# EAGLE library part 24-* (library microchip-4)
Serial EEPROM 32 K/64 K, 1.8 V, I2C
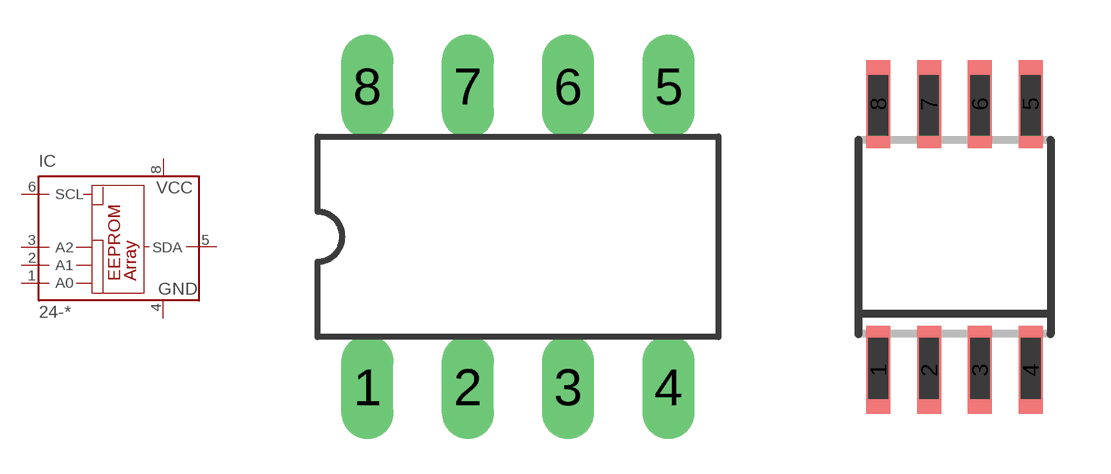
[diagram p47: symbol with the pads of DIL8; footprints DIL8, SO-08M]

Designator prefix IC

## 24-AA65P, 24-C32P, 24-C65P, 24-FC32P, 24-FC65P, 24-LC32P, 24-LC65P  [DIL8]
1  A0  in
2  A1  in
3  A2  in
4  GND  pwr
5  SDA
6  SCL  in
8  VCC  pwr

## 24-AA65SM, 24-C32SM, 24-C65SM, 24-FC32SM, 24-FC65SM, 24-LC32SM, 24-LC65SM  [SO-08M]
Pads as for DIL8

## Footprint DIL8 (pad centres in mm)
Dual In Line package type P
drill 0.813 long: 1 -3.81,-3.81; 2 -1.27,-3.81; 3 1.27,-3.81; 4 3.81,-3.81; 5 3.81,3.81; 6 1.27,3.81; 7 -1.27,3.81; 8 -3.81,3.81

## Footprint SO-08M (pad centres in mm)
Small Outline Medium Plastic Gull Wing 207-mil body, package type SM
smd 0.6 x 2.2: 1 -1.905,-3.33; 2 -0.635,-3.33; 3 0.635,-3.33; 4 1.905,-3.33; 5 1.905,3.33; 6 0.635,3.33; 7 -0.635,3.33; 8 -1.905,3.33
